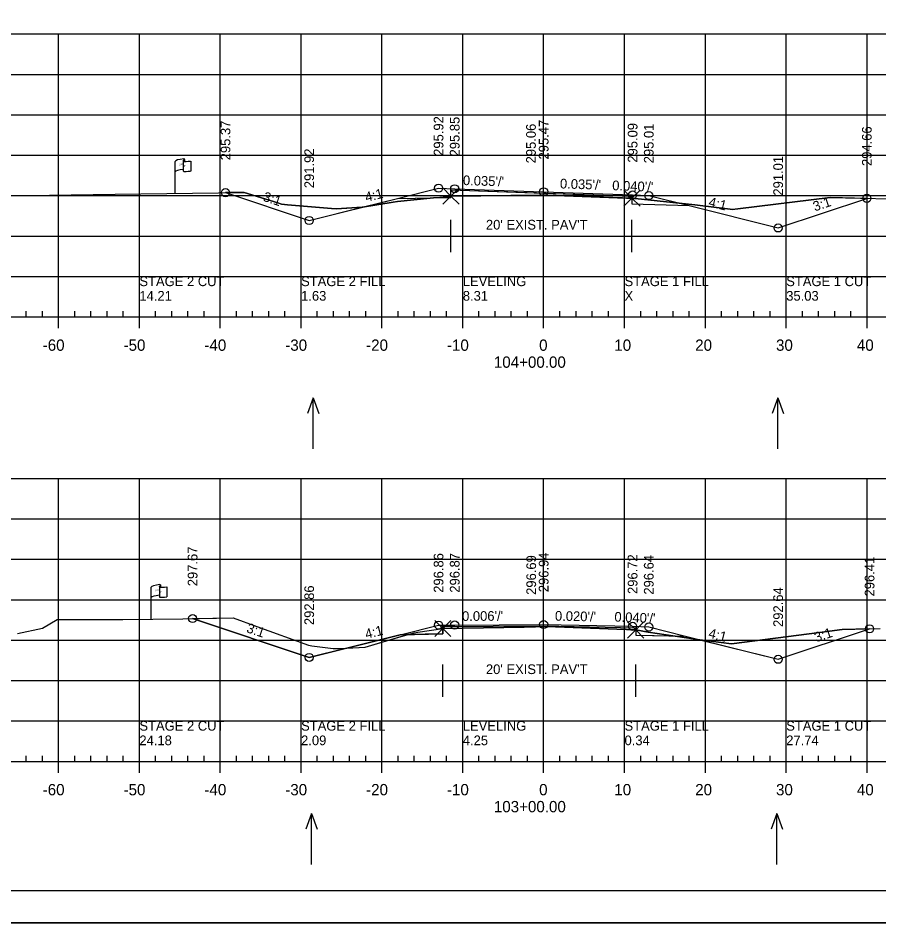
# Model space of a CAD drawing. Extents: x 1370843 to 1371177, y 380307 to 382654.
# Drawn here: x 1370948.7 to 1371055.2, y 380520.8 to 380632.8 of the extents above; entities that cross this region are included whole.
import ezdxf

# ---------------------------------------------------------------- set-up
doc = ezdxf.new("R2010")
doc.units = 0
for name, color, linetype in [('R_Alt Surface', 7, 'Continuous'), ('R_Axis', 7, 'Continuous'), ('R_Axis Annot', 7, 'Continuous'), ('R_Border', 7, 'Continuous'), ('R_Exist Surface', 7, 'Continuous'), ('R_Exist Surface Annot', 7, 'Continuous'), ('R_Fin Surface', 7, 'Continuous'), ('R_Fin Surface Annot', 7, 'Continuous'), ('R_Grid', 7, 'Continuous'), ('R_No Plot', 7, 'Continuous'), ('R_ROW', 7, 'Continuous'), ('R_Water Annot', 7, 'Continuous'), ('R_Xsect Elev', 7, 'Continuous')]:
    doc.layers.add(name, color=color, linetype=linetype)

msp = doc.modelspace()

# ---------------------------------------------------------------- linework, layer by layer
at = {"layer": 'R_Alt Surface'}
for points in [[(1370995.63, 380610.44), (1371002.24, 380610.57), (1371002.24, 380611.49), (1371013.71, 380611.09), (1371024.63, 380610.71), (1371024.63, 380609.79), (1371031.7, 380609.55)], [(1370995.97, 380556.46), (1371001.24, 380556.57), (1371001.24, 380557.48), (1371013.71, 380557.55), (1371025.1, 380557.33), (1371025.1, 380556.41), (1371031.25, 380556.29)]]:
    msp.add_lwpolyline(points, dxfattribs=at)
at = {"layer": 'R_Axis'}
for p, q in [((1370949.71, 380595.79), (1370949.71, 380596.49)), ((1370951.71, 380595.79), (1370951.71, 380596.49)), ((1370955.71, 380595.79), (1370955.71, 380596.49)), ((1370957.71, 380595.79), (1370957.71, 380596.49)), ((1370959.71, 380595.79), (1370959.71, 380596.49)), ((1370961.71, 380595.79), (1370961.71, 380596.49)), ((1370965.71, 380595.79), (1370965.71, 380596.49)), ((1370967.71, 380595.79), (1370967.71, 380596.49)), ((1370969.71, 380595.79), (1370969.71, 380596.49)), ((1370971.71, 380595.79), (1370971.71, 380596.49)), ((1370975.71, 380595.79), (1370975.71, 380596.49)), ((1370977.71, 380595.79), (1370977.71, 380596.49)), ((1370979.71, 380595.79), (1370979.71, 380596.49)), ((1370981.71, 380595.79), (1370981.71, 380596.49)), ((1370985.71, 380595.79), (1370985.71, 380596.49)), ((1370987.71, 380595.79), (1370987.71, 380596.49)), ((1370989.71, 380595.79), (1370989.71, 380596.49)), ((1370991.71, 380595.79), (1370991.71, 380596.49)), ((1370995.71, 380595.79), (1370995.71, 380596.49)), ((1370997.71, 380595.79), (1370997.71, 380596.49)), ((1370999.71, 380595.79), (1370999.71, 380596.49)), ((1371001.71, 380595.79), (1371001.71, 380596.49)), ((1371005.71, 380595.79), (1371005.71, 380596.49)), ((1371007.71, 380595.79), (1371007.71, 380596.49)), ((1371009.71, 380595.79), (1371009.71, 380596.49)), ((1371011.71, 380595.79), (1371011.71, 380596.49)), ((1371015.71, 380595.79), (1371015.71, 380596.49)), ((1371017.71, 380595.79), (1371017.71, 380596.49)), ((1371019.71, 380595.79), (1371019.71, 380596.49)), ((1371021.71, 380595.79), (1371021.71, 380596.49)), ((1371025.71, 380595.79), (1371025.71, 380596.49)), ((1371027.71, 380595.79), (1371027.71, 380596.49)), ((1371029.71, 380595.79), (1371029.71, 380596.49)), ((1371031.71, 380595.79), (1371031.71, 380596.49)), ((1371035.71, 380595.79), (1371035.71, 380596.49)), ((1371037.71, 380595.79), (1371037.71, 380596.49)), ((1371039.71, 380595.79), (1371039.71, 380596.49)), ((1371041.71, 380595.79), (1371041.71, 380596.49)), ((1371045.71, 380595.79), (1371045.71, 380596.49)), ((1371047.71, 380595.79), (1371047.71, 380596.49)), ((1371049.71, 380595.79), (1371049.71, 380596.49)), ((1371051.71, 380595.79), (1371051.71, 380596.49)), ((1370868.71, 380595.79), (1371158.71, 380595.79)), ((1370953.71, 380594.39), (1370953.71, 380595.79)), ((1370963.71, 380594.39), (1370963.71, 380595.79)), ((1370973.71, 380594.39), (1370973.71, 380595.79)), ((1370983.71, 380594.39), (1370983.71, 380595.79)), ((1370993.71, 380594.39), (1370993.71, 380595.79)), ((1371003.71, 380594.39), (1371003.71, 380595.79)), ((1371013.71, 380594.39), (1371013.71, 380595.79)), ((1371023.71, 380594.39), (1371023.71, 380595.79)), ((1371033.71, 380594.39), (1371033.71, 380595.79)), ((1371043.71, 380594.39), (1371043.71, 380595.79)), ((1371053.71, 380594.39), (1371053.71, 380595.79)), ((1370949.71, 380540.79), (1370949.71, 380541.49)), ((1370951.71, 380540.79), (1370951.71, 380541.49)), ((1370955.71, 380540.79), (1370955.71, 380541.49)), ((1370957.71, 380540.79), (1370957.71, 380541.49)), ((1370959.71, 380540.79), (1370959.71, 380541.49)), ((1370961.71, 380540.79), (1370961.71, 380541.49)), ((1370965.71, 380540.79), (1370965.71, 380541.49)), ((1370967.71, 380540.79), (1370967.71, 380541.49)), ((1370969.71, 380540.79), (1370969.71, 380541.49)), ((1370971.71, 380540.79), (1370971.71, 380541.49)), ((1370975.71, 380540.79), (1370975.71, 380541.49)), ((1370977.71, 380540.79), (1370977.71, 380541.49)), ((1370979.71, 380540.79), (1370979.71, 380541.49)), ((1370981.71, 380540.79), (1370981.71, 380541.49)), ((1370985.71, 380540.79), (1370985.71, 380541.49)), ((1370987.71, 380540.79), (1370987.71, 380541.49)), ((1370989.71, 380540.79), (1370989.71, 380541.49)), ((1370991.71, 380540.79), (1370991.71, 380541.49)), ((1370995.71, 380540.79), (1370995.71, 380541.49)), ((1370997.71, 380540.79), (1370997.71, 380541.49)), ((1370999.71, 380540.79), (1370999.71, 380541.49)), ((1371001.71, 380540.79), (1371001.71, 380541.49)), ((1371005.71, 380540.79), (1371005.71, 380541.49)), ((1371007.71, 380540.79), (1371007.71, 380541.49)), ((1371009.71, 380540.79), (1371009.71, 380541.49)), ((1371011.71, 380540.79), (1371011.71, 380541.49)), ((1371015.71, 380540.79), (1371015.71, 380541.49)), ((1371017.71, 380540.79), (1371017.71, 380541.49)), ((1371019.71, 380540.79), (1371019.71, 380541.49)), ((1371021.71, 380540.79), (1371021.71, 380541.49)), ((1371025.71, 380540.79), (1371025.71, 380541.49)), ((1371027.71, 380540.79), (1371027.71, 380541.49)), ((1371029.71, 380540.79), (1371029.71, 380541.49)), ((1371031.71, 380540.79), (1371031.71, 380541.49)), ((1371035.71, 380540.79), (1371035.71, 380541.49)), ((1371037.71, 380540.79), (1371037.71, 380541.49)), ((1371039.71, 380540.79), (1371039.71, 380541.49)), ((1371041.71, 380540.79), (1371041.71, 380541.49)), ((1371045.71, 380540.79), (1371045.71, 380541.49)), ((1371047.71, 380540.79), (1371047.71, 380541.49)), ((1371049.71, 380540.79), (1371049.71, 380541.49)), ((1371051.71, 380540.79), (1371051.71, 380541.49)), ((1370868.71, 380540.79), (1371158.71, 380540.79)), ((1370953.71, 380539.39), (1370953.71, 380540.79)), ((1370963.71, 380539.39), (1370963.71, 380540.79)), ((1370973.71, 380539.39), (1370973.71, 380540.79)), ((1370983.71, 380539.39), (1370983.71, 380540.79)), ((1370993.71, 380539.39), (1370993.71, 380540.79)), ((1371003.71, 380539.39), (1371003.71, 380540.79)), ((1371013.71, 380539.39), (1371013.71, 380540.79)), ((1371023.71, 380539.39), (1371023.71, 380540.79)), ((1371033.71, 380539.39), (1371033.71, 380540.79)), ((1371043.71, 380539.39), (1371043.71, 380540.79)), ((1371053.71, 380539.39), (1371053.71, 380540.79))]:
    msp.add_line(p, q, dxfattribs=at)
at = {"layer": 'R_Border'}
msp.add_line((1371171.89, 380524.79), (1370855.71, 380524.79), dxfattribs=at)
at = {"layer": 'R_Exist Surface'}
for points in [[(1370930.84, 380610.5), (1370960.73, 380610.95), (1370976.65, 380611.19), (1370980.83, 380609.88), (1370981.28, 380609.72), (1370982.04, 380609.63), (1370987.45, 380609.18), (1370988.06, 380609.17), (1370991.29, 380609.35), (1370995.08, 380609.97), (1370995.63, 380610.07), (1371001.7, 380610.69), (1371002.24, 380610.74), (1371013.38, 380610.84), (1371014.12, 380610.84), (1371023.96, 380610.49), (1371024.63, 380610.47), (1371025.03, 380610.42), (1371032.42, 380609.65), (1371036.78, 380609.1), (1371037.03, 380609.07), (1371037.72, 380609.16), (1371049.16, 380610.54), (1371056.65, 380610.39)], [(1370948.65, 380556.63), (1370951.71, 380557.27), (1370953.53, 380558.36), (1370961.66, 380558.33), (1370969.08, 380558.44), (1370975.29, 380558.53), (1370978.24, 380557.46), (1370984.61, 380555.18), (1370985.04, 380555.07), (1370987.66, 380554.74), (1370988.48, 380554.76), (1370991.62, 380554.94), (1370996.1, 380556.25), (1370997.68, 380556.71), (1370998.16, 380556.77), (1371001.24, 380557.23), (1371011.31, 380557.4), (1371014.11, 380557.47), (1371022.77, 380557.14), (1371025.1, 380557.05), (1371026.64, 380556.78), (1371032.19, 380555.94), (1371034.39, 380555.68), (1371036.96, 380555.35), (1371047.82, 380556.72), (1371050.64, 380557.1), (1371055.31, 380557.23)]]:
    msp.add_lwpolyline(points, dxfattribs=at)
at = {"layer": 'R_Exist Surface Annot'}
for p, q in [((1371002.24, 380603.79), (1371002.24, 380607.79)), ((1371024.63, 380603.79), (1371024.63, 380607.79)), ((1371002.24, 380605.79), (1371024.63, 380605.79)), ((1371001.24, 380548.79), (1371001.24, 380552.79)), ((1371025.1, 380548.79), (1371025.1, 380552.79)), ((1371001.24, 380550.79), (1371025.1, 380550.79))]:
    msp.add_line(p, q, dxfattribs=at)
at = {"layer": 'R_Fin Surface'}
for points in [[(1370974.36, 380611.16), (1370984.7, 380607.71), (1370984.71, 380607.71), (1370995.63, 380610.44), (1371000.71, 380611.71), (1371002.71, 380611.64), (1371013.71, 380611.26), (1371024.71, 380610.87), (1371026.71, 380610.79), (1371031.7, 380609.55), (1371042.71, 380606.79), (1371053.68, 380610.45)], [(1370970.29, 380558.46), (1370984.7, 380553.65), (1370984.71, 380553.65), (1370995.97, 380556.46), (1371000.71, 380557.65), (1371002.71, 380557.66), (1371013.71, 380557.72), (1371024.71, 380557.5), (1371026.71, 380557.42), (1371031.25, 380556.29), (1371042.71, 380553.42), (1371054.02, 380557.19)]]:
    msp.add_lwpolyline(points, dxfattribs=at)
at = {"layer": 'R_Grid'}
for p, q in [((1370868.71, 380630.79), (1371158.71, 380630.79)), ((1370953.71, 380595.79), (1370953.71, 380630.79)), ((1370963.71, 380595.79), (1370963.71, 380630.79)), ((1370973.71, 380595.79), (1370973.71, 380630.79)), ((1370983.71, 380595.79), (1370983.71, 380630.79)), ((1370993.71, 380595.79), (1370993.71, 380630.79)), ((1371003.71, 380595.79), (1371003.71, 380630.79)), ((1371013.71, 380595.79), (1371013.71, 380630.79)), ((1371023.71, 380595.79), (1371023.71, 380630.79)), ((1371033.71, 380595.79), (1371033.71, 380630.79)), ((1371043.71, 380595.79), (1371043.71, 380630.79)), ((1371053.71, 380595.79), (1371053.71, 380630.79)), ((1370868.71, 380625.79), (1371158.71, 380625.79)), ((1370868.71, 380620.79), (1371158.71, 380620.79)), ((1370868.71, 380615.79), (1371158.71, 380615.79)), ((1370868.71, 380610.79), (1371158.71, 380610.79)), ((1370868.71, 380605.79), (1371158.71, 380605.79)), ((1370868.71, 380600.79), (1371158.71, 380600.79)), ((1370868.71, 380595.79), (1371158.71, 380595.79)), ((1370868.71, 380575.79), (1371158.71, 380575.79)), ((1370953.71, 380540.79), (1370953.71, 380575.79)), ((1370963.71, 380540.79), (1370963.71, 380575.79)), ((1370973.71, 380540.79), (1370973.71, 380575.79)), ((1370983.71, 380540.79), (1370983.71, 380575.79)), ((1370993.71, 380540.79), (1370993.71, 380575.79)), ((1371003.71, 380540.79), (1371003.71, 380575.79)), ((1371013.71, 380540.79), (1371013.71, 380575.79)), ((1371023.71, 380540.79), (1371023.71, 380575.79)), ((1371033.71, 380540.79), (1371033.71, 380575.79)), ((1371043.71, 380540.79), (1371043.71, 380575.79)), ((1371053.71, 380540.79), (1371053.71, 380575.79)), ((1370868.71, 380570.79), (1371158.71, 380570.79)), ((1370868.71, 380565.79), (1371158.71, 380565.79)), ((1370868.71, 380560.79), (1371158.71, 380560.79)), ((1370868.71, 380555.79), (1371158.71, 380555.79)), ((1370868.71, 380550.79), (1371158.71, 380550.79)), ((1370868.71, 380545.79), (1371158.71, 380545.79)), ((1370868.71, 380540.79), (1371158.71, 380540.79))]:
    msp.add_line(p, q, dxfattribs=at)
at = {"layer": 'R_No Plot'}
msp.add_line((1370843.31, 380520.81), (1371176.64, 380520.81), dxfattribs=at)
for points in [[(1370843.3, 380734.14), (1371176.64, 380734.14), (1371176.64, 380520.8), (1370843.3, 380520.8)], [(1371089.63, 380730.25), (1371089.63, 380720.37), (1371125.36, 380720.37), (1371125.36, 380717.45), (1371148.56, 380717.45), (1371148.56, 380693.11), (1371171.89, 380693.11), (1371171.89, 380524.79), (1370855.71, 380524.79), (1370855.71, 380730.25)], [(1370974.36, 380611.16), (1370984.71, 380607.71), (1370991.28, 380609.35), (1370988.06, 380609.17), (1370987.45, 380609.18), (1370982.04, 380609.63), (1370981.28, 380609.72), (1370980.83, 380609.88), (1370976.65, 380611.19)], [(1371000.1, 380610.53), (1371001.7, 380610.69), (1371002.24, 380610.74), (1371002.24, 380610.57)], [(1371013.38, 380610.84), (1371002.24, 380610.74), (1371002.24, 380611.49), (1371024.63, 380610.71), (1371024.63, 380610.47), (1371014.12, 380610.84)], [(1370991.29, 380609.35), (1370991.28, 380609.35), (1370995.63, 380610.44), (1371000.1, 380610.53), (1370995.63, 380610.07), (1370995.08, 380609.97)], [(1371024.63, 380610.47), (1371024.63, 380609.79), (1371031.7, 380609.55), (1371042.71, 380606.79), (1371053.68, 380610.45), (1371049.16, 380610.54), (1371037.72, 380609.16), (1371037.03, 380609.07), (1371036.78, 380609.1), (1371032.42, 380609.65), (1371025.03, 380610.42)], [(1370970.29, 380558.46), (1370975.29, 380558.53), (1370978.24, 380557.46), (1370984.61, 380555.18), (1370985.04, 380555.07), (1370987.66, 380554.74), (1370988.48, 380554.76), (1370989.36, 380554.81), (1370984.71, 380553.65)], [(1370996.88, 380556.48), (1370997.68, 380556.71), (1370998.16, 380556.77), (1371001.24, 380557.23), (1371001.24, 380556.57)], [(1371001.24, 380557.23), (1371001.24, 380557.48), (1371013.71, 380557.55), (1371025.1, 380557.33), (1371025.1, 380557.05), (1371022.77, 380557.14), (1371014.11, 380557.47), (1371011.31, 380557.4)], [(1371025.1, 380557.05), (1371025.1, 380556.41), (1371029.7, 380556.32), (1371026.64, 380556.78)], [(1371033.02, 380555.84), (1371042.71, 380553.42), (1371054.02, 380557.19), (1371050.64, 380557.1), (1371047.82, 380556.72), (1371036.96, 380555.35), (1371034.39, 380555.68)], [(1370989.36, 380554.81), (1370991.62, 380554.94), (1370996.88, 380556.48), (1370995.97, 380556.46)], [(1371029.7, 380556.32), (1371031.25, 380556.29), (1371033.02, 380555.84), (1371032.19, 380555.94)]]:
    msp.add_lwpolyline(points, close=True, dxfattribs=at)
for points in [[(1371002.24, 380610.74), (1371001.24, 380611.74), (1371002.24, 380610.74), (1371001.24, 380609.74), (1371002.24, 380610.74), (1371003.24, 380609.74), (1371002.24, 380610.74), (1371003.24, 380611.74)], [(1371024.63, 380610.47), (1371023.63, 380611.47), (1371024.63, 380610.47), (1371023.63, 380609.47), (1371024.63, 380610.47), (1371025.63, 380609.47), (1371024.63, 380610.47), (1371025.63, 380611.47)], [(1371001.24, 380557.23), (1371000.24, 380558.23), (1371001.24, 380557.23), (1371000.24, 380556.23), (1371001.24, 380557.23), (1371002.24, 380556.23), (1371001.24, 380557.23), (1371002.24, 380558.23)], [(1371025.1, 380557.05), (1371024.1, 380558.05), (1371025.1, 380557.05), (1371024.1, 380556.05), (1371025.1, 380557.05), (1371026.1, 380556.05), (1371025.1, 380557.05), (1371026.1, 380558.05)]]:
    msp.add_lwpolyline(points, dxfattribs=at)
for centre in [(1371000.71, 380611.71), (1371002.71, 380611.64), (1371013.71, 380611.26), (1370974.36, 380611.16), (1371024.71, 380610.87), (1371026.71, 380610.79), (1371053.68, 380610.45), (1370984.71, 380607.71), (1371042.71, 380606.79), (1370970.29, 380558.46), (1371000.71, 380557.65), (1371002.71, 380557.66), (1371013.71, 380557.72), (1371024.71, 380557.5), (1371026.71, 380557.42), (1371054.02, 380557.19), (1370984.71, 380553.65), (1371042.71, 380553.42)]:
    msp.add_circle(centre, 0.5, dxfattribs=at)
at = {"layer": 'R_ROW'}
for p, q in [((1370969.12, 380615.11), (1370969.12, 380615.09)), ((1370969.12, 380615.09), (1370969.12, 380613.87)), ((1370969.29, 380615.26), (1370969.29, 380615.02)), ((1370970.06, 380615.07), (1370970.06, 380613.83)), ((1370968.12, 380611.06), (1370968.12, 380615.01)), ((1370966.34, 380562.58), (1370966.34, 380562.34)), ((1370965.18, 380558.38), (1370965.18, 380562.33)), ((1370966.18, 380562.42), (1370966.18, 380562.41)), ((1370966.18, 380562.41), (1370966.18, 380561.18)), ((1370967.11, 380562.39), (1370967.11, 380561.15))]:
    msp.add_line(p, q, dxfattribs=at)
for centre, radius, start, end in [((1370969.2, 380615.11), 0.078, 88.6458, 274.2828), ((1370969.21, 380615.26), 0.0783, 263.0712, 93.9564), ((1370969.2, 380613.87), 0.0783, 180, 273.9564), ((1370966.25, 380562.42), 0.078, 88.6458, 274.2828), ((1370966.27, 380562.58), 0.0783, 263.0712, 93.9564), ((1370966.25, 380561.18), 0.0783, 180, 273.9564)]:
    msp.add_arc(centre, radius, start, end, dxfattribs=at)
for centre, major_axis, ratio, start_param, end_param in [((1370969.71, 380615.05), (-1.58, -0.04), 0.19887, 5.030368, 6.283185), ((1370970.41, 380615.17), (-1.23, -0.13), 0.052933, 0.159456, 1.268315), ((1370969.7, 380613.74), (-1.58, -0.04), 0.19887, 5.083035, 6.194897), ((1370970.41, 380613.93), (-1.23, -0.13), 0.052933, 0.159456, 1.268315), ((1370966.76, 380562.37), (-1.58, -0.04), 0.19887, 5.030368, 6.283185), ((1370966.76, 380561.06), (-1.58, -0.04), 0.19887, 5.083035, 6.194897), ((1370967.47, 380562.49), (-1.23, -0.13), 0.052933, 0.159456, 1.268315), ((1370967.47, 380561.25), (-1.23, -0.13), 0.052933, 0.159456, 1.268315)]:
    msp.add_ellipse(centre, major_axis=major_axis, ratio=ratio, start_param=start_param, end_param=end_param, dxfattribs=at)
at = {"layer": 'R_Water Annot'}
for p, q in [((1370985.19, 380585.77), (1370984.49, 380583.84)), ((1370985.19, 380579.48), (1370985.19, 380585.77)), ((1370985.19, 380585.77), (1370985.89, 380583.84)), ((1371042.69, 380585.77), (1371041.99, 380583.84)), ((1371042.69, 380579.48), (1371042.69, 380585.77)), ((1371042.69, 380585.77), (1371043.39, 380583.84)), ((1370984.99, 380534.32), (1370984.29, 380532.39)), ((1370984.99, 380528.03), (1370984.99, 380534.32)), ((1370984.99, 380534.32), (1370985.69, 380532.39)), ((1371042.54, 380534.32), (1371041.84, 380532.39)), ((1371042.54, 380528.03), (1371042.54, 380534.32)), ((1371042.54, 380534.32), (1371043.24, 380532.39))]:
    msp.add_line(p, q, dxfattribs=at)

# ---------------------------------------------------------------- texts
at = {"layer": 'R_Axis Annot'}
for s, p in [('-60', (1370951.75, 380591.59)), ('-50', (1370961.75, 380591.59)), ('-40', (1370971.75, 380591.59)), ('-30', (1370981.75, 380591.59)), ('-20', (1370991.75, 380591.59)), ('-10', (1371001.75, 380591.59)), ('0', (1371013.15, 380591.59)), ('10', (1371022.45, 380591.59)), ('20', (1371032.45, 380591.59)), ('30', (1371042.45, 380591.59)), ('40', (1371052.45, 380591.59)), ('104+00.00', (1371007.55, 380589.49)), ('-60', (1370951.75, 380536.59)), ('-50', (1370961.75, 380536.59)), ('-40', (1370971.75, 380536.59)), ('-30', (1370981.75, 380536.59)), ('-20', (1370991.75, 380536.59)), ('-10', (1371001.75, 380536.59)), ('0', (1371013.15, 380536.59)), ('10', (1371022.45, 380536.59)), ('20', (1371032.45, 380536.59)), ('30', (1371042.45, 380536.59)), ('40', (1371052.45, 380536.59)), ('103+00.00', (1371007.55, 380534.49))]:
    msp.add_text(s, height=1.4, dxfattribs=at).set_placement(p)
at = {"layer": 'R_Exist Surface Annot'}
for p in [(1371006.57, 380606.59), (1371006.57, 380551.59)]:
    msp.add_text("20' EXIST. PAV'T", height=1.2, dxfattribs=at).set_placement(p)
at = {"layer": 'R_Fin Surface Annot'}
for s, rotation, p in [('295.37', 90, (1370974.96, 380615.16)), ('295.92', 90, (1371001.31, 380615.71)), ('295.85', 90, (1371003.31, 380615.64)), ('295.47', 90, (1371014.31, 380615.26)), ('295.09', 90, (1371025.31, 380614.87)), ('295.01', 90, (1371027.31, 380614.79)), ('294.66', 90, (1371054.28, 380614.45)), ('291.92', 90, (1370985.31, 380611.71)), ('291.01', 90, (1371043.31, 380610.79)), ("0.035'/'", 358.006, (1371003.71, 380612.1)), ("0.035'/'", 358.006, (1371015.71, 380611.69)), ("0.040'/'", 357.7094, (1371022.17, 380611.47)), ('3:1', 341.5651, (1370978.91, 380610.17)), ('4:1', 14.0362, (1370991.78, 380609.99)), ('4:1', 345.9638, (1371034.02, 380609.48)), ('3:1', 18.4349, (1371047.25, 380608.83)), ('297.67', 90, (1370970.89, 380562.46)), ('296.86', 90, (1371001.31, 380561.65)), ('296.87', 90, (1371003.31, 380561.66)), ('296.94', 90, (1371014.31, 380561.72)), ('296.72', 90, (1371025.31, 380561.5)), ('296.64', 90, (1371027.31, 380561.42)), ('296.41', 90, (1371054.62, 380561.19)), ('292.86', 90, (1370985.31, 380557.65)), ('292.64', 90, (1371043.31, 380557.42)), ("0.006'/'", 0.3267, (1371003.62, 380558.16)), ("0.020'/'", 358.8542, (1371015.1, 380558.2)), ("0.040'/'", 357.7094, (1371022.44, 380558.09)), ('3:1', 341.5651, (1370976.87, 380556.79)), ('4:1', 14.0362, (1370991.78, 380555.93)), ('4:1', 345.9638, (1371034.02, 380556.11)), ('3:1', 18.4349, (1371047.42, 380555.52))]:
    msp.add_text(s, height=1.2, rotation=rotation, dxfattribs=at).set_placement(p)
at = {"layer": 'R_No Plot'}
for s, p in [('STAGE 2 CUT', (1370963.71, 380599.59)), ('STAGE 2 FILL', (1370983.71, 380599.59)), ('LEVELING', (1371003.71, 380599.59)), ('STAGE 1 FILL', (1371023.71, 380599.59)), ('STAGE 1 CUT', (1371043.71, 380599.59)), ('14.21', (1370963.71, 380597.79)), ('1.63', (1370983.71, 380597.79)), ('8.31', (1371003.71, 380597.79)), ('X', (1371023.71, 380597.79)), ('35.03', (1371043.71, 380597.79)), ('STAGE 2 CUT', (1370963.71, 380544.59)), ('STAGE 2 FILL', (1370983.71, 380544.59)), ('LEVELING', (1371003.71, 380544.59)), ('STAGE 1 FILL', (1371023.71, 380544.59)), ('STAGE 1 CUT', (1371043.71, 380544.59)), ('24.18', (1370963.71, 380542.79)), ('2.09', (1370983.71, 380542.79)), ('4.25', (1371003.71, 380542.79)), ('0.34', (1371023.71, 380542.79)), ('27.74', (1371043.71, 380542.79))]:
    msp.add_text(s, height=1.2, dxfattribs=at).set_placement(p)
at = {"layer": 'R_ROW'}
for s, height, rotation, p in [('R ', 0.2, 9.9884, (1370968.64, 380614.51)), (' O', 0.2, 9.9884, (1370968.79, 380614.56)), ('W', 0.2, 351.1788, (1370969.12, 380614.39)), ('DWB 11-9-07', 0.001, 90, (1370969.29, 380615.02)), ('DWB 11-9-07', 0.001, 5.0717, (1370970.05, 380613.83)), ('DWB 11-9-07', 0.001, 90, (1370968.12, 380611.06)), ('R ', 0.2, 9.9884, (1370965.7, 380561.83)), (' O', 0.2, 9.9884, (1370965.85, 380561.88)), ('W', 0.2, 351.1788, (1370966.18, 380561.71)), ('DWB 11-9-07', 0.001, 90, (1370966.34, 380562.34)), ('DWB 11-9-07', 0.001, 5.0717, (1370967.1, 380561.15)), ('DWB 11-9-07', 0.001, 90, (1370965.18, 380558.38))]:
    msp.add_text(s, height=height, rotation=rotation, dxfattribs=at).set_placement(p)
at = {"layer": 'R_Xsect Elev'}
for s, p in [('295.06', (1371012.74, 380614.78)), ('296.69', (1371012.77, 380561.39))]:
    msp.add_text(s, height=1.2, rotation=90, dxfattribs=at).set_placement(p)

doc.saveas('drawing.dxf')
